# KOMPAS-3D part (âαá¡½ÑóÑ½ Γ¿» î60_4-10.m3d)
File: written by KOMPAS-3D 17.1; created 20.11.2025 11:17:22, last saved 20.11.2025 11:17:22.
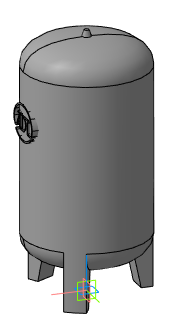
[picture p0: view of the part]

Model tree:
1. Операция без истории:4

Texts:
  REVIT MATERIAL OVERRIDDEN
  REVIT MATERIAL ID
  REVIT SUBCATEGORY ID
  REVIT CATEGORY ID
  REVIT ELEMENT ID
  REVIT BREP TAG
